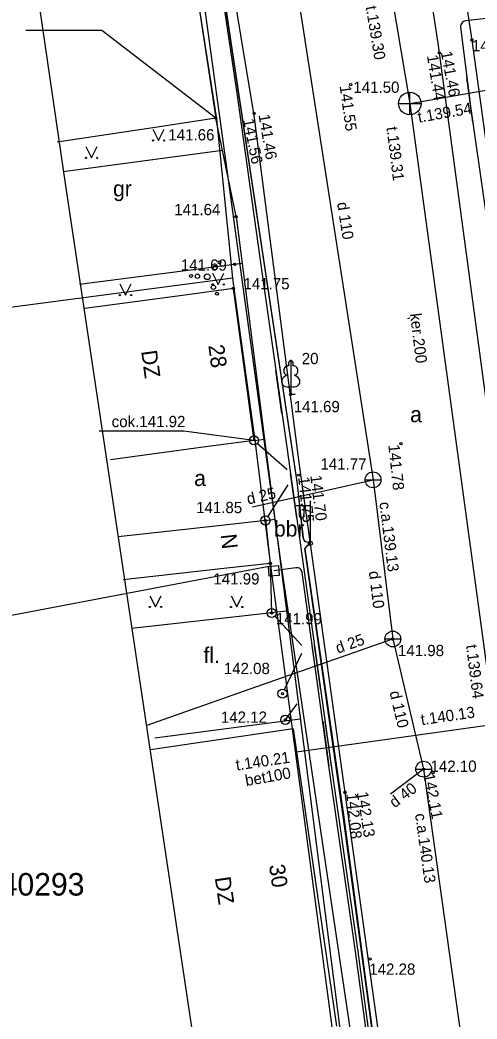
# Model space of a CAD drawing. Extents: x 728710 to 728960, y 272811 to 273475.
# Drawn here: x 728808.9 to 728829.17, y 273033.26 to 273077.6 of the extents above; entities that cross this region are included whole.
import ezdxf

# ---------------------------------------------------------------- set-up
doc = ezdxf.new("R2010")
doc.units = 0
for name, color, linetype in [('GEOD_ELEM_####_TKST_#', 7, 'Continuous'), ('Level 15', 7, 'Continuous'), ('Level 17', 7, 'Continuous'), ('Level 23', 7, 'Continuous'), ('Level 26', 7, 'Continuous'), ('Level 28', 7, 'Continuous'), ('Level 29', 7, 'Continuous'), ('Level 3', 7, 'Continuous'), ('Level 36', 7, 'Continuous'), ('Level 39', 7, 'Continuous'), ('Level 4', 7, 'Continuous'), ('Level 43', 7, 'Continuous'), ('Level 48', 7, 'Continuous'), ('Level 50', 7, 'Continuous'), ('Level 55', 7, 'Continuous'), ('Level 56', 7, 'Continuous'), ('Level 57', 7, 'Continuous'), ('Level 58', 7, 'Continuous'), ('Level 59', 7, 'Continuous'), ('Level 60', 7, 'Continuous'), ('Level 62', 7, 'Continuous'), ('Level 9', 7, 'Continuous'), ('PNTNO', 7, 'Continuous'), ('RAMI_UZMR_####_####_#', 7, 'Continuous'), ('RELJ_ELEM_####_####_#', 7, 'Continuous'), ('RELJ_NOGA_####_####_#', 7, 'Continuous'), ('ROBZ_ELEM_####_####_#', 7, 'Continuous'), ('ROBZ_KADS_####_TKST_#', 7, 'Continuous'), ('ROBZ_UZMR_####_####_#', 7, 'Continuous'), ('TERT_ELEM_####_####_#', 7, 'Continuous'), ('TERT_KONT_####_####_#', 7, 'Continuous')]:
    doc.layers.add(name, color=color, linetype=linetype)

msp = doc.modelspace()

# ---------------------------------------------------------------- linework, layer by layer
at = {"layer": 'GEOD_ELEM_####_TKST_#'}
for points in [[(728821.778, 273054.372), (728821.536, 273054.45), (728821.45, 273054.614), (728821.201, 273057.003), (728816.435, 273088.774), (728813.852, 273106.392), (728813.783, 273106.59), (728812.551, 273107.084)], [(728828.856, 273003.445), (728828.68, 273003.642), (728828.556, 273003.935), (728824.783, 273030.792), (728823.249, 273042.16), (728821.524, 273054.142), (728821.778, 273054.372)]]:
    msp.add_lwpolyline(points, dxfattribs=at)
at = {"layer": 'Level 15'}
msp.add_lwpolyline([(728820.398, 273052.949), (728819.953, 273052.907), (728819.912, 273053.345), (728820.357, 273053.387)], close=True, dxfattribs=at)
at = {"layer": 'Level 17'}
for p, q in [((728819.209, 273055.986), (728824.557, 273057.19)), ((728819.112, 273047.909), (728825.433, 273050.125)), ((728814.495, 273046.291), (728819.112, 273047.909)), ((728826.802, 273044.347), (728825.336, 273043.229))]:
    msp.add_line(p, q, dxfattribs=at)
for points in [[(728820.62, 273082.615), (728824.557, 273057.19)], [(728824.557, 273057.19), (728825.433, 273050.125)], [(728825.433, 273050.125), (728826.802, 273044.347)], [(728826.802, 273044.347), (728830.203, 273020.034)]]:
    msp.add_lwpolyline(points, dxfattribs=at)
at = {"layer": 'Level 23'}
for points in [[(728821.624, 273100.995), (728826.189, 273073.896), (728840.452, 273076.388)], [(728826.189, 273073.896), (728833.694, 273018.747), (728821.168, 273017.069)], [(728829.942, 273046.322), (728821.163, 273045.101)]]:
    msp.add_lwpolyline(points, dxfattribs=at)
at = {"layer": 'Level 26'}
for p, q in [((728821.778, 273054.372), (728821.778, 273056.255)), ((728821.778, 273056.039), (728821.143, 273056.034)), ((728821.278, 273056.035), (728821.278, 273055.643)), ((728821.488, 273056.037), (728821.488, 273055.643))]:
    msp.add_line(p, q, dxfattribs=at)
msp.add_circle((728821.778, 273054.372), 0.09, dxfattribs=at)
msp.add_ellipse((728821.383, 273055.643), major_axis=(0, 0.151), ratio=0.695971, start_param=1.570796, end_param=4.712389, dxfattribs=at)
at = {"layer": 'Level 28'}
msp.add_lwpolyline([(728819.996, 273053.478), (728820.058, 273051.281)], dxfattribs=at)
at = {"layer": 'Level 29'}
for p, q in [((728826.189, 273073.396), (728826.189, 273074.396)), ((728825.689, 273073.896), (728826.689, 273073.896))]:
    msp.add_line(p, q, dxfattribs=at)
msp.add_circle((728826.189, 273073.896), 0.5, dxfattribs=at)
at = {"layer": 'Level 3'}
for p, q in [((728814.857, 273091.278), (728817.584, 273073.242)), ((728817.584, 273073.242), (728815.181, 273072.879)), ((728815.181, 273072.879), (728810.55, 273072.18)), ((728816.109, 273065.377), (728811.767, 273064.787)), ((728818.361, 273065.683), (728816.109, 273065.377)), ((728819.278, 273058.939), (728818.361, 273065.683)), ((728819.278, 273058.939), (728817.021, 273058.632)), ((728817.021, 273058.632), (728812.904, 273058.072)), ((728819.784, 273055.383), (728817.7, 273055.151)), ((728819.784, 273055.383), (728819.996, 273053.478)), ((728817.7, 273055.151), (728813.255, 273054.657)), ((728819.996, 273053.478), (728818.068, 273053.263)), ((728818.068, 273053.263), (728813.467, 273052.751)), ((728821.012, 273046.132), (728814.687, 273045.208)), ((728821.012, 273046.132), (728822.94, 273032.932))]:
    msp.add_line(p, q, dxfattribs=at)
at = {"layer": 'Level 36'}
for p, q in [((728822.135, 273047.837), (728821.862, 273049.816)), ((728822.323, 273046.47), (728822.596, 273044.484))]:
    msp.add_line(p, q, dxfattribs=at)
for points in [[(728828.98, 273073.067), (728828.721, 273075.05)], [(728820.514, 273060.139), (728820.244, 273062.047)], [(728821.172, 273055.494), (728820.891, 273057.472)], [(728822.234, 273047.85), (728821.961, 273049.829)], [(728822.422, 273046.483), (728822.695, 273044.498)]]:
    msp.add_lwpolyline(points, dxfattribs=at)
at = {"layer": 'Level 39'}
for p, q in [((728824.206, 273057.19), (728824.908, 273057.19)), ((728824.556, 273057.19), (728824.556, 273057.191)), ((728825.082, 273050.125), (728825.784, 273050.125)), ((728825.432, 273050.125), (728825.432, 273050.126)), ((728826.451, 273044.347), (728827.153, 273044.347)), ((728826.801, 273044.347), (728826.801, 273044.348))]:
    msp.add_line(p, q, dxfattribs=at)
for centre in [(728824.557, 273057.19), (728825.433, 273050.125), (728826.802, 273044.347)]:
    msp.add_circle(centre, 0.351, dxfattribs=at)
at = {"layer": 'Level 4'}
for p, q in [((728818.479, 273068.87), (728817.584, 273073.242)), ((728818.479, 273068.87), (728819.741, 273058.998)), ((728819.278, 273058.939), (728819.741, 273058.998)), ((728819.784, 273055.383), (728820.196, 273055.436)), ((728820.196, 273055.436), (728823.604, 273028.739)), ((728820.717, 273051.354), (728818.488, 273051.106)), ((728818.488, 273051.106), (728813.845, 273050.59))]:
    msp.add_line(p, q, dxfattribs=at)
for points in [[(728845.654, 273100.85), (728832.719, 273098.413), (728826.071, 273097.316), (728825.017, 273097.001), (728824.765, 273096.832), (728824.532, 273096.455), (728824.532, 273096.455), (728826.161, 273084.877), (728827.437, 273076.575), (728829.749, 273059.3), (728831.728, 273043.761), (728834.021, 273027.538), (728834.782, 273021.709), (728836.279, 273011.943), (728839.357, 272993.501), (728839.499, 272992.383), (728841.21, 272978.381), (728843.301, 272966.86), (728843.797, 272965.94)], [(728845.919, 273099.374), (728832.98, 273096.936), (728826.409, 273095.852), (728826.143, 273095.772), (728827.647, 273085.083), (728828.941, 273076.709), (728831.314, 273059.418), (728833.202, 273044.226), (728835.526, 273027.512), (728836.266, 273021.924), (728837.76, 273012.18), (728840.331, 272994.327), (728840.331, 272994.327), (728840.331, 272994.327), (728842.687, 272979.229), (728844.615, 272968.066)], [(728791.727, 273091.506), (728811.654, 273095.023), (728814.654, 273095.178), (728815.22, 273095.032), (728815.785, 273094.657), (728816.384, 273093.154), (728816.384, 273093.154), (728817.477, 273084.163), (728819.263, 273073.354), (728821.261, 273057.957), (728825.757, 273025.679), (728827.763, 273011.141), (728832.943, 272977.993), (728834.913, 272963.328)], [(728817.878, 273071.807), (728810.815, 273070.864)], [(728818.747, 273066.786), (728811.536, 273065.866)], [(728819.741, 273058.998), (728820.196, 273055.436)], [(728814.879, 273045.732), (728821.326, 273046.586)]]:
    msp.add_lwpolyline(points, dxfattribs=at)
at = {"layer": 'Level 43'}
for p, q in [((728819.428, 273058.807), (728820.751, 273057.648)), ((728819.892, 273055.551), (728820.798, 273056.962)), ((728820.194, 273051.134), (728821.404, 273049.831)), ((728820.627, 273047.882), (728821.404, 273049.5)), ((728820.669, 273046.536), (728821.191, 273047.252))]:
    msp.add_line(p, q, dxfattribs=at)
for centre in [(728819.278, 273058.939), (728819.784, 273055.383), (728820.058, 273051.281), (728820.54, 273047.702), (728820.669, 273046.536)]:
    msp.add_circle(centre, 0.202, dxfattribs=at)
at = {"layer": 'Level 48'}
for centre in [(728828.941, 273076.709), (728827.497, 273076.14), (728823.568, 273074.734), (728819.282, 273073.459), (728817.584, 273073.242), (728818.479, 273068.87), (728818.423, 273066.749), (728818.361, 273065.683), (728820.908, 273060.984), (728825.798, 273058.791), (728821.261, 273057.396), (728819.784, 273055.383), (728819.996, 273053.478), (728820.058, 273051.281), (728825.433, 273050.125), (728820.54, 273047.702), (728820.669, 273046.536), (728826.802, 273044.347), (728827.212, 273044.194), (728823.315, 273043.313), (728824.421, 273035.923)]:
    msp.add_circle(centre, 0.05, dxfattribs=at)
at = {"layer": 'Level 9'}
for points in [[(728817.584, 273073.242), (728812.529, 273077.127), (728809.159, 273077.127)], [(728819.278, 273058.939), (728816.159, 273059.355), (728812.414, 273059.355)]]:
    msp.add_lwpolyline(points, dxfattribs=at)
at = {"layer": 'RAMI_UZMR_####_####_#'}
msp.add_lwpolyline([(728788.892, 273161.497), (728790.999, 273149.932), (728793.805, 273144.064), (728799.858, 273144.727), (728801.765, 273127.417), (728785.623, 273117.349), (728785.888, 273114.234), (728788.818, 273102.829), (728792.114, 273090.001), (728794.527, 273084.256), (728808.426, 273087.287), (728810.894, 273070.336), (728816.634, 273032.011)], dxfattribs=at)
at = {"layer": 'RELJ_ELEM_####_####_#'}
for points in [[(728812.551, 273107.084), (728813.167, 273106.837), (728813.712, 273106.629), (728813.818, 273106.491), (728816.417, 273088.868), (728821.181, 273057.115), (728821.45, 273054.614), (728821.507, 273054.486), (728821.778, 273054.372)], [(728821.778, 273054.372), (728821.586, 273054.209), (728821.524, 273054.142), (728821.54, 273054.018), (728823.24, 273042.315), (728824.783, 273030.792), (728828.544, 273004.011), (728828.618, 273003.789), (728828.856, 273003.445)]]:
    msp.add_lwpolyline(points, dxfattribs=at)
at = {"layer": 'ROBZ_ELEM_####_####_#'}
msp.add_lwpolyline([(728815.186, 273091.969), (728820.435, 273053.684), (728833.431, 272966.054)], dxfattribs=at)
at = {"layer": 'ROBZ_UZMR_####_####_#'}
for p, q in [((728817.629, 273073.203), (728814.807, 273091.306)), ((728818.333, 273066.14), (728817.629, 273073.203)), ((728818.333, 273066.14), (728802.21, 273064.008)), ((728818.39, 273065.68), (728818.333, 273066.14)), ((728819.34, 273058.83), (728818.39, 273065.68)), ((728820.023, 273053.364), (728819.34, 273058.83)), ((728802.379, 273050.028), (728820.023, 273053.364)), ((728823.179, 273029.707), (728820.023, 273053.364))]:
    msp.add_line(p, q, dxfattribs=at)
at = {"layer": 'TERT_ELEM_####_####_#'}
for points in [[(728815.267, 273094.223), (728815.717, 273091.871), (728816.832, 273085.52), (728817.881, 273078.643), (728818.508, 273074.355), (728819.658, 273066.192), (728820.712, 273058.74), (728821.479, 273053.332), (728822.695, 273044.505), (728823.883, 273036.26), (728825.025, 273027.716), (728825.927, 273020.849), (728826.755, 273015.106), (728828.259, 273004.946), (728828.26, 273004.941)], [(728843.881, 273079.951), (728838.722, 273078.96), (728834.933, 273078.385), (728830.885, 273077.81), (728828.661, 273077.556)], [(728828.441, 273077.276), (728828.896, 273073.653), (728830.094, 273065.295), (728831.248, 273056.446), (728832.388, 273048.159)], [(728821.131, 273053.283), (728820.155, 273053.147)], [(728825.79, 273021.122), (728824.925, 273027.702), (728823.783, 273036.246), (728822.595, 273044.491), (728821.414, 273053.07)]]:
    msp.add_lwpolyline(points, dxfattribs=at)
for centre, start, end in [((728828.69, 273077.307), 96.5231, 187.1505), ((728821.166, 273053.036), 7.8436, 97.9537)]:
    msp.add_arc(centre, 0.25, start, end, dxfattribs=at)
at = {"layer": 'TERT_KONT_####_####_#'}
for p, q in [((728814.791, 273072.752), (728815.041, 273072.252)), ((728815.041, 273072.252), (728815.291, 273072.752)), ((728811.819, 273071.984), (728812.069, 273071.484)), ((728812.069, 273071.484), (728812.319, 273071.984)), ((728817.442, 273066.365), (728817.692, 273065.865)), ((728817.692, 273065.865), (728817.942, 273066.365)), ((728813.326, 273065.891), (728813.576, 273065.391)), ((728813.576, 273065.391), (728813.826, 273065.891)), ((728820.908, 273061.331), (728820.908, 273060.984)), ((728820.908, 273060.984), (728821.108, 273060.984)), ((728814.657, 273052.046), (728814.907, 273051.546)), ((728814.907, 273051.546), (728815.157, 273052.046)), ((728818.258, 273052.046), (728818.508, 273051.546)), ((728818.508, 273051.546), (728818.758, 273052.046))]:
    msp.add_line(p, q, dxfattribs=at)
for points in [[(728820.908, 273062.484), (728820.908, 273061.331)], [(728820.998, 273062.252), (728820.997, 273062.253)]]:
    msp.add_lwpolyline(points, dxfattribs=at)
for centre, radius in [((728814.791, 273072.252), 0.028), ((728815.291, 273072.252), 0.0263), ((728811.819, 273071.483), 0.028), ((728812.319, 273071.483), 0.0263), ((728817.548, 273066.611), 0.096), ((728817.745, 273066.843), 0.064), ((728816.482, 273066.238), 0.064), ((728816.767, 273066.224), 0.096), ((728817.201, 273066.204), 0.128), ((728817.477, 273065.737), 0.096), ((728817.441, 273065.864), 0.028), ((728817.941, 273065.864), 0.0263), ((728813.326, 273065.39), 0.028), ((728813.826, 273065.39), 0.0263), ((728817.635, 273065.447), 0.064), ((728814.656, 273051.545), 0.028), ((728815.156, 273051.545), 0.0263), ((728818.257, 273051.545), 0.028), ((728818.757, 273051.545), 0.0263)]:
    msp.add_circle(centre, radius, dxfattribs=at)
for centre, major_axis, ratio, start_param, end_param in [((728820.78, 273062.039), (-0.039, -0.212), 0.861323, 3.141593, 6.283185), ((728820.908, 273062.334), (0, -0.15), 0.707107, 3.14537, 5.287485), ((728820.908, 273062.334), (0, -0.15), 0.707107, 0.995701, 3.137816), ((728821.036, 273062.039), (0.039, -0.212), 0.861323, 0, 3.141593), ((728820.818, 273061.577), (0.307, 0.095), 0.814445, 1.570796, 4.752015), ((728820.998, 273061.577), (-0.307, 0.095), 0.814445, 1.531171, 4.712389)]:
    msp.add_ellipse(centre, major_axis=major_axis, ratio=ratio, start_param=start_param, end_param=end_param, dxfattribs=at)

# ---------------------------------------------------------------- texts
at = {"layer": 'Level 50'}
msp.add_text('cok.141.92', height=0.5, dxfattribs=at).set_placement((728812.963, 273059.527))
at = {"layer": 'Level 55'}
for s, rotation, p in [('d 110', 278.8022, (728822.958, 273069.479)), ('d 25', 12.6875, (728819.016, 273056.089)), ('c.a.139.13', 277.0681, (728824.833, 273056.179)), ('d 110', 277.0681, (728824.367, 273053.114)), ('d 25', 19.3165, (728822.999, 273049.468)), ('d 110', 283.3295, (728825.281, 273047.762)), ('d 40', 37.3298, (728825.516, 273042.605)), ('c.a.140.13', 277.9631, (728826.415, 273042.35))]:
    msp.add_text(s, height=0.5, rotation=rotation, dxfattribs=at).set_placement(p)
at = {"layer": 'Level 56'}
msp.add_text(' 141.50', height=0.5, dxfattribs=at).set_placement((728823.498, 273074.365))
at = {"layer": 'Level 57'}
for s, p in [('141.46', (728828.941, 273076.209)), (' 141.66', (728815.291, 273072.252)), (' 141.64', (728815.553, 273068.936)), (' 141.69', (728815.842, 273066.473)), (' 141.75', (728818.623, 273065.644)), (' 141.69', (728820.852, 273060.19)), (' 141.85', (728816.521, 273055.711)), (' 141.99', (728817.288, 273052.544)), (' 141.99', (728820.057, 273050.773)), (' 142.08', (728817.75, 273048.566)), (' 142.12', (728817.62, 273046.405)), (' 142.28', (728824.203, 273035.219))]:
    msp.add_text(s, height=0.5, dxfattribs=at).set_placement(p)
for s, rotation, p in [('141.44', 279.1375, (728826.946, 273076.016)), ('141.46', 280.7495, (728827.558, 273076.171)), ('141.55', 277.7616, (728823.073, 273074.666)), ('141.46', 279.6159, (728819.473, 273073.384)), ('141.56', 281.2924, (728818.784, 273073.174)), ('141.78', 276.0185, (728825.234, 273058.735)), ('141.75', 276.119, (728821.234, 273057.3)), ('141.70', 277.0868, (728821.772, 273057.373)), ('142.11', 281.0116, (728826.785, 273044.105)), ('142.08', 275.6262, (728823.369, 273043.263)), ('142.13', 279.2446, (728823.833, 273043.308))]:
    msp.add_text(s, height=0.5, rotation=rotation, dxfattribs=at).set_placement(p)
at = {"layer": 'Level 58'}
for s, p in [('gr', (728813.025, 273069.767)), ('a', (728826.203, 273059.747)), ('a', (728816.623, 273056.912)), ('bbr', (728820.162, 273054.67)), ('fl.', (728817.037, 273049.055))]:
    msp.add_text(s, height=0.7, dxfattribs=at).set_placement(p)
at = {"layer": 'Level 59'}
for s, rotation, p in [('DZ', 277.743, (728814.269, 273062.899)), ('N', 276.349, (728817.797, 273054.753)), ('DZ', 278.31, (728817.534, 273039.529))]:
    msp.add_text(s, height=0.7, rotation=rotation, dxfattribs=at).set_placement(p)
at = {"layer": 'Level 60'}
for s, rotation, p in [('t.139.30', 279.562, (728824.227, 273078.183)), ('t.139.54', 9.909, (728826.589, 273073.035)), ('t.139.31', 277.044, (728825.152, 273072.833)), ('ķer.200', 277.044, (728826.192, 273064.552)), ('t.139.64', 277.044, (728828.683, 273049.845)), ('t.140.13', 8.314, (728826.711, 273046.294)), ('t.140.21', 8.314, (728818.505, 273044.286)), ('bet100', 10.055, (728818.928, 273043.591))]:
    msp.add_text(s, height=0.5, rotation=rotation, dxfattribs=at).set_placement(p)
at = {"layer": 'Level 62'}
for s, rotation, p in [('28', 277.743, (728817.248, 273063.151)), ('30', 278.31, (728819.939, 273040.08))]:
    msp.add_text(s, height=0.7, rotation=rotation, dxfattribs=at).set_placement(p)
at = {"layer": 'PNTNO'}
for s, p in [(' 141.77', (728822.036, 273057.642)), (' 141.98', (728825.476, 273049.363)), (' 142.10', (728826.92, 273044.227))]:
    msp.add_text(s, height=0.5, dxfattribs=at).set_placement(p)
at = {"layer": 'RELJ_NOGA_####_####_#'}
msp.add_text('20', height=0.5, dxfattribs=at).set_placement((728821.395, 273062.322))
at = {"layer": 'ROBZ_KADS_####_TKST_#'}
msp.add_text('68010040293', height=1, dxfattribs=at).set_placement((728803.575, 273038.735))

doc.saveas('drawing.dxf')
